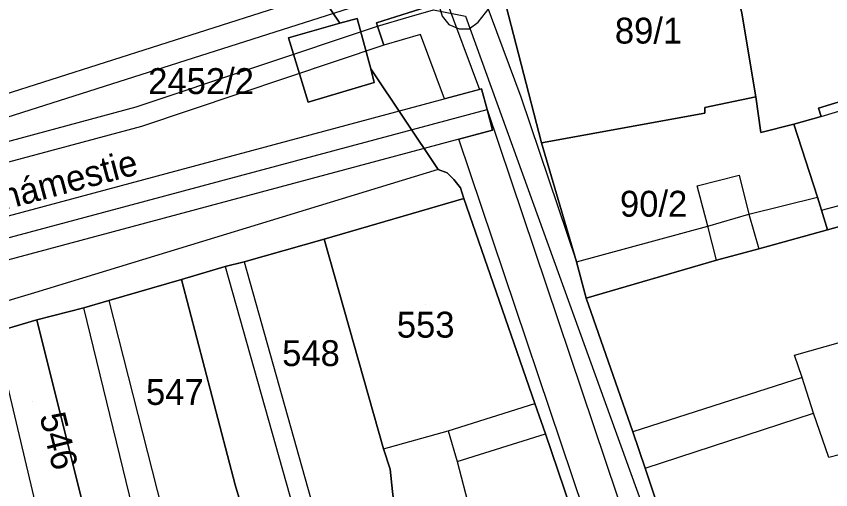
# Model space of a CAD drawing. Extents: x -263423 to -261326, y -1240067 to -1237864.
# Drawn here: x -262980.7 to -262917.7, y -1239574.4 to -1239537.8 of the extents above; entities that cross this region are included whole.
import ezdxf

# ---------------------------------------------------------------- set-up
doc = ezdxf.new("R2010")
doc.units = 0
for name, color, linetype in [('body_kn', 7, 'Continuous'), ('kladpar_druhypozemkov', 7, 'Continuous'), ('kladpar_hranice', 7, 'Continuous'), ('kladpar_parcelnecisla', 7, 'Continuous'), ('kladpar_plochy', 7, 'Continuous'), ('kladpar_sipky', 7, 'Continuous'), ('popisy', 7, 'Continuous'), ('tarchy_linie', 7, 'Continuous'), ('zappar_hrandruhpozemk', 7, 'Continuous')]:
    doc.layers.add(name, color=color, linetype=linetype)

msp = doc.modelspace()

# ---------------------------------------------------------------- linework, layer by layer
at = {"layer": 'body_kn'}
for p, q in [((-262954.35, -1239537.98), (-262954.35, -1239537.98)), ((-262950.32, -1239537.86), (-262950.32, -1239537.86)), ((-262955.69, -1239538.35), (-262955.69, -1239538.35)), ((-262955.69, -1239538.35), (-262955.69, -1239538.35)), ((-262952.85, -1239538.33), (-262952.85, -1239538.33)), ((-262952.77, -1239538.58), (-262952.77, -1239538.58)), ((-262952.77, -1239538.58), (-262952.77, -1239538.58)), ((-262947.27, -1239538.46), (-262947.27, -1239538.46)), ((-262946.45, -1239538.78), (-262946.45, -1239538.78)), ((-262946.45, -1239538.78), (-262946.45, -1239538.78)), ((-262945.68, -1239538.79), (-262945.68, -1239538.79)), ((-262944.98, -1239538.28), (-262944.98, -1239538.28)), ((-262949.46, -1239539.22), (-262949.46, -1239539.22)), ((-262959.65, -1239539.48), (-262959.65, -1239539.48)), ((-262952.28, -1239540.05), (-262952.28, -1239540.05)), ((-262953.28, -1239541.87), (-262953.28, -1239541.87)), ((-262953.03, -1239542.95), (-262953.03, -1239542.95)), ((-262944.88, -1239543.48), (-262944.88, -1239543.48)), ((-262944.73, -1239543.44), (-262944.73, -1239543.44)), ((-262958.13, -1239544.45), (-262958.13, -1239544.45)), ((-262947.59, -1239544.21), (-262947.59, -1239544.21)), ((-262941.68, -1239544.05), (-262941.68, -1239544.05)), ((-262923.51, -1239544.06), (-262923.51, -1239544.06)), ((-262923.51, -1239544.06), (-262923.51, -1239544.06)), ((-262971.43, -1239544.83), (-262971.43, -1239544.83)), ((-262944.3, -1239545.03), (-262944.3, -1239545.03)), ((-262944.3, -1239545.03), (-262944.3, -1239545.03)), ((-262927.47, -1239544.87), (-262927.47, -1239544.87)), ((-262918.67, -1239544.92), (-262918.67, -1239544.92)), ((-262927.47, -1239545.32), (-262927.47, -1239545.32)), ((-262918.48, -1239545.56), (-262918.48, -1239545.56)), ((-262918.48, -1239545.56), (-262918.48, -1239545.56)), ((-262971.03, -1239546.33), (-262971.03, -1239546.33)), ((-262920.57, -1239546.15), (-262920.57, -1239546.15)), ((-262943.87, -1239546.62), (-262943.87, -1239546.62)), ((-262923.14, -1239546.81), (-262923.14, -1239546.81)), ((-262946.48, -1239547.32), (-262946.48, -1239547.32)), ((-262940.1, -1239547.61), (-262940.1, -1239547.61)), ((-262940.1, -1239547.61), (-262940.1, -1239547.61)), ((-262948.08, -1239549.67), (-262948.08, -1239549.67)), ((-262948.08, -1239549.67), (-262948.08, -1239549.67)), ((-262947.38, -1239549.93), (-262947.38, -1239549.93)), ((-262924.81, -1239550.11), (-262924.81, -1239550.11)), ((-262946.87, -1239550.44), (-262946.87, -1239550.44)), ((-262946.36, -1239551.08), (-262946.36, -1239551.08)), ((-262928.06, -1239550.92), (-262928.06, -1239550.92)), ((-262946.11, -1239551.91), (-262946.11, -1239551.91)), ((-262946.11, -1239551.91), (-262946.11, -1239551.91)), ((-262918.76, -1239551.8), (-262918.76, -1239551.8)), ((-262924.05, -1239553.11), (-262924.05, -1239553.11)), ((-262918.44, -1239552.82), (-262918.44, -1239552.82)), ((-262918.44, -1239552.82), (-262918.44, -1239552.82)), ((-262927.24, -1239554.05), (-262927.24, -1239554.05)), ((-262917.99, -1239554.32), (-262917.99, -1239554.32)), ((-262917.99, -1239554.32), (-262917.99, -1239554.32)), ((-262956.89, -1239555.04), (-262956.89, -1239555.04)), ((-262923.3, -1239555.79), (-262923.3, -1239555.79)), ((-262963.09, -1239556.79), (-262963.09, -1239556.79)), ((-262963.09, -1239556.79), (-262963.09, -1239556.79)), ((-262937.39, -1239556.8), (-262937.39, -1239556.8)), ((-262937.39, -1239556.8), (-262937.39, -1239556.8)), ((-262926.55, -1239556.66), (-262926.55, -1239556.66)), ((-262926.55, -1239556.66), (-262926.55, -1239556.66)), ((-262964.55, -1239557.16), (-262964.55, -1239557.16)), ((-262964.55, -1239557.16), (-262964.55, -1239557.16)), ((-262967.94, -1239558.17), (-262967.94, -1239558.17)), ((-262967.94, -1239558.17), (-262967.94, -1239558.17)), ((-262979.29, -1239559.19), (-262979.29, -1239559.19)), ((-262973.55, -1239559.79), (-262973.55, -1239559.79)), ((-262973.55, -1239559.79), (-262973.55, -1239559.79)), ((-262936.63, -1239559.6), (-262936.63, -1239559.6)), ((-262975.47, -1239560.36), (-262975.47, -1239560.36)), ((-262979.11, -1239561.29), (-262979.11, -1239561.29)), ((-262920.52, -1239564.02), (-262920.52, -1239564.02)), ((-262920.52, -1239564.02), (-262920.52, -1239564.02)), ((-262919.95, -1239565.74), (-262919.95, -1239565.74)), ((-262919.95, -1239565.74), (-262919.95, -1239565.74)), ((-262940.62, -1239567.74), (-262940.62, -1239567.74)), ((-262919.07, -1239568.49), (-262919.07, -1239568.49)), ((-262947.32, -1239569.87), (-262947.32, -1239569.87)), ((-262939.79, -1239570.1), (-262939.79, -1239570.1)), ((-262933.04, -1239569.94), (-262933.04, -1239569.94)), ((-262952.3, -1239571.25), (-262952.3, -1239571.25)), ((-262952.3, -1239571.25), (-262952.3, -1239571.25)), ((-262917.87, -1239571.93), (-262917.87, -1239571.93)), ((-262946.62, -1239572.23), (-262946.62, -1239572.23)), ((-262932.09, -1239572.75), (-262932.09, -1239572.75)), ((-262932.09, -1239572.75), (-262932.09, -1239572.75)), ((-262951.79, -1239572.84), (-262951.79, -1239572.84)), ((-262963.78, -1239574.05), (-262963.78, -1239574.05))]:
    msp.add_line(p, q, dxfattribs=at)
at = {"layer": 'kladpar_druhypozemkov'}
for p, q in [((-262955.77, -1239541.66), (-262955.77, -1239541.66)), ((-262931.45, -1239551.21), (-262931.45, -1239551.21)), ((-262949.06, -1239560.12), (-262949.06, -1239560.12)), ((-262958.07, -1239562.56), (-262958.07, -1239562.56)), ((-262968.77, -1239565.66), (-262968.77, -1239565.66)), ((-262979.47, -1239567.56), (-262979.47, -1239567.56))]:
    msp.add_line(p, q, dxfattribs=at)
at = {"layer": 'kladpar_hranice'}
for points in [[(-262935.95, -1239581.4), (-262939.79, -1239570.1), (-262940.62, -1239567.74), (-262946.11, -1239551.91), (-262946.36, -1239551.08), (-262946.87, -1239550.44), (-262947.38, -1239549.93), (-262948.08, -1239549.67), (-262953.28, -1239541.87), (-262954.35, -1239537.98), (-262955.69, -1239538.35), (-262964.64, -1239525.12), (-262966.02, -1239520.78), (-262966.85, -1239521.03), (-262967.56, -1239521.21), (-262969.22, -1239521.78), (-262984.05, -1239464.66)], [(-262965.51, -1239465.42), (-262962.58, -1239476.73), (-262961.82, -1239479.55), (-262957.93, -1239492.91), (-262955.74, -1239500.08), (-262954.99, -1239502.36), (-262952.85, -1239509), (-262951.27, -1239514.04), (-262950.07, -1239517.61), (-262948.43, -1239523.23), (-262945.27, -1239531.91), (-262943.25, -1239535.42), (-262940.1, -1239547.61), (-262937.39, -1239556.8), (-262936.63, -1239559.6), (-262933.04, -1239569.94), (-262932.09, -1239572.75), (-262928.43, -1239583.67)], [(-262964.64, -1239525.12), (-262955.69, -1239538.35), (-262959.65, -1239539.48), (-262958.13, -1239544.45), (-262953.03, -1239542.95), (-262953.28, -1239541.87), (-262948.08, -1239549.67), (-262947.38, -1239549.93), (-262946.87, -1239550.44), (-262946.36, -1239551.08), (-262946.11, -1239551.91), (-262956.89, -1239555.04), (-262963.09, -1239556.79), (-262964.55, -1239557.16), (-262967.94, -1239558.17), (-262973.55, -1239559.79), (-262975.47, -1239560.36), (-262979.11, -1239561.29), (-262982.36, -1239562.23)], [(-262923.51, -1239544.06), (-262927.47, -1239544.87), (-262927.47, -1239545.32), (-262940.1, -1239547.61), (-262943.25, -1239535.42), (-262926.24, -1239530.63)], [(-262926.24, -1239530.63), (-262924.6, -1239537.58), (-262923.51, -1239544.06)], [(-262923.51, -1239544.06), (-262924.6, -1239537.58), (-262926.24, -1239530.63)], [(-262869.06, -1239540.52), (-262844.5, -1239533.52), (-262841.03, -1239544.11), (-262840.53, -1239545.7), (-262836.49, -1239558.34), (-262849.7, -1239561.9), (-262861.12, -1239565.66), (-262879.23, -1239570.41), (-262884.4, -1239571.98), (-262891.48, -1239573.92), (-262893.14, -1239574.42), (-262895.06, -1239574.86), (-262928.43, -1239583.67), (-262932.09, -1239572.75), (-262933.04, -1239569.94), (-262936.63, -1239559.6), (-262926.55, -1239556.66), (-262923.3, -1239555.79), (-262917.99, -1239554.32), (-262895.92, -1239548.22), (-262869.06, -1239540.52)], [(-262955.69, -1239538.35), (-262954.35, -1239537.98), (-262953.28, -1239541.87), (-262953.03, -1239542.95), (-262958.13, -1239544.45), (-262959.65, -1239539.48), (-262955.69, -1239538.35)], [(-262913.95, -1239543.48), (-262918.67, -1239544.92), (-262918.48, -1239545.56), (-262920.57, -1239546.15), (-262923.14, -1239546.81), (-262923.51, -1239544.06)], [(-262917.99, -1239554.32), (-262918.44, -1239552.82), (-262918.76, -1239551.8), (-262920.57, -1239546.15), (-262918.48, -1239545.56), (-262918.67, -1239544.92), (-262913.95, -1239543.48)], [(-262940.1, -1239547.61), (-262927.47, -1239545.32), (-262927.47, -1239544.87), (-262923.51, -1239544.06), (-262923.14, -1239546.81), (-262920.57, -1239546.15), (-262918.76, -1239551.8), (-262918.44, -1239552.82), (-262917.99, -1239554.32), (-262923.3, -1239555.79), (-262926.55, -1239556.66), (-262936.63, -1239559.6), (-262937.39, -1239556.8), (-262940.1, -1239547.61)], [(-262895.92, -1239548.22), (-262917.99, -1239554.32)], [(-262946.11, -1239551.91), (-262940.62, -1239567.74), (-262939.79, -1239570.1), (-262935.95, -1239581.4), (-262945.07, -1239583.13), (-262944.44, -1239584.67), (-262949.54, -1239585.6), (-262950.55, -1239581.32), (-262951.11, -1239578.71), (-262951.61, -1239574.56), (-262951.79, -1239572.84), (-262952.3, -1239571.25), (-262956.89, -1239555.04), (-262946.11, -1239551.91)], [(-262952.3, -1239571.25), (-262951.79, -1239572.84), (-262951.61, -1239574.56), (-262951.11, -1239578.71), (-262950.55, -1239581.32), (-262949.54, -1239585.6), (-262954.9, -1239586.97), (-262959.31, -1239588.09), (-262960.31, -1239584.2), (-262960.63, -1239583.05), (-262961.07, -1239583.05), (-262963.03, -1239576.54), (-262963.78, -1239574.05), (-262967.94, -1239558.17), (-262964.55, -1239557.16), (-262963.09, -1239556.79), (-262956.89, -1239555.04), (-262952.3, -1239571.25)], [(-262967.94, -1239558.17), (-262963.78, -1239574.05), (-262963.03, -1239576.54), (-262961.07, -1239583.05), (-262960.63, -1239583.05), (-262960.31, -1239584.2), (-262959.31, -1239588.09), (-262971.11, -1239591.16), (-262972.25, -1239587.01), (-262974.89, -1239578.2), (-262979.11, -1239561.29), (-262975.47, -1239560.36), (-262973.55, -1239559.79), (-262967.94, -1239558.17)], [(-262974.89, -1239578.2), (-262972.25, -1239587.01), (-262971.11, -1239591.16), (-262976.09, -1239593.1), (-262977.35, -1239588.89), (-262980.13, -1239579.7), (-262985.3, -1239563.04), (-262982.36, -1239562.23), (-262979.11, -1239561.29), (-262974.89, -1239578.2)]]:
    msp.add_lwpolyline(points, dxfattribs=at)
at = {"layer": 'kladpar_plochy'}
for points in [[(-262935.95, -1239581.4), (-262939.79, -1239570.1), (-262940.62, -1239567.74), (-262946.11, -1239551.91), (-262946.36, -1239551.08), (-262946.87, -1239550.44), (-262947.38, -1239549.93), (-262948.08, -1239549.67), (-262953.28, -1239541.87), (-262954.35, -1239537.98), (-262955.69, -1239538.35), (-262964.64, -1239525.12), (-262966.02, -1239520.78), (-262966.85, -1239521.03), (-262967.56, -1239521.21), (-262969.22, -1239521.78), (-262984.05, -1239464.66)], [(-262965.51, -1239465.42), (-262962.58, -1239476.73), (-262961.82, -1239479.55), (-262957.93, -1239492.91), (-262955.74, -1239500.08), (-262954.99, -1239502.36), (-262952.85, -1239509), (-262951.27, -1239514.04), (-262950.07, -1239517.61), (-262948.43, -1239523.23), (-262945.27, -1239531.91), (-262943.25, -1239535.42), (-262940.1, -1239547.61), (-262937.39, -1239556.8), (-262936.63, -1239559.6), (-262933.04, -1239569.94), (-262932.09, -1239572.75), (-262928.43, -1239583.67)], [(-262964.64, -1239525.12), (-262955.69, -1239538.35), (-262959.65, -1239539.48), (-262958.13, -1239544.45), (-262953.03, -1239542.95), (-262953.28, -1239541.87), (-262948.08, -1239549.67), (-262947.38, -1239549.93), (-262946.87, -1239550.44), (-262946.36, -1239551.08), (-262946.11, -1239551.91), (-262956.89, -1239555.04), (-262963.09, -1239556.79), (-262964.55, -1239557.16), (-262967.94, -1239558.17), (-262973.55, -1239559.79), (-262975.47, -1239560.36), (-262979.11, -1239561.29), (-262982.36, -1239562.23)], [(-262895.92, -1239548.22), (-262917.99, -1239554.32), (-262918.44, -1239552.82), (-262918.76, -1239551.8), (-262920.57, -1239546.15), (-262918.48, -1239545.56), (-262918.67, -1239544.92), (-262913.95, -1239543.48)]]:
    msp.add_lwpolyline(points, dxfattribs=at)
for points in [[(-262917.14, -1239528.13), (-262916.09, -1239533.53), (-262916.62, -1239533.75), (-262914.63, -1239540.59), (-262913.95, -1239543.48), (-262918.67, -1239544.92), (-262918.48, -1239545.56), (-262920.57, -1239546.15), (-262923.14, -1239546.81), (-262923.51, -1239544.06), (-262924.6, -1239537.58), (-262926.24, -1239530.63)], [(-262926.24, -1239530.63), (-262924.6, -1239537.58), (-262923.51, -1239544.06), (-262927.47, -1239544.87), (-262927.47, -1239545.32), (-262940.1, -1239547.61), (-262943.25, -1239535.42)], [(-262869.06, -1239540.52), (-262844.5, -1239533.52), (-262841.03, -1239544.11), (-262840.53, -1239545.7), (-262836.49, -1239558.34), (-262849.7, -1239561.9), (-262861.12, -1239565.66), (-262879.23, -1239570.41), (-262884.4, -1239571.98), (-262891.48, -1239573.92), (-262893.14, -1239574.42), (-262895.06, -1239574.86), (-262928.43, -1239583.67), (-262932.09, -1239572.75), (-262933.04, -1239569.94), (-262936.63, -1239559.6), (-262926.55, -1239556.66), (-262923.3, -1239555.79), (-262917.99, -1239554.32), (-262895.92, -1239548.22)], [(-262955.69, -1239538.35), (-262954.35, -1239537.98), (-262953.28, -1239541.87), (-262953.03, -1239542.95), (-262958.13, -1239544.45), (-262959.65, -1239539.48)], [(-262940.1, -1239547.61), (-262927.47, -1239545.32), (-262927.47, -1239544.87), (-262923.51, -1239544.06), (-262923.14, -1239546.81), (-262920.57, -1239546.15), (-262918.76, -1239551.8), (-262918.44, -1239552.82), (-262917.99, -1239554.32), (-262923.3, -1239555.79), (-262926.55, -1239556.66), (-262936.63, -1239559.6), (-262937.39, -1239556.8)], [(-262946.11, -1239551.91), (-262940.62, -1239567.74), (-262939.79, -1239570.1), (-262935.95, -1239581.4), (-262945.07, -1239583.13), (-262944.44, -1239584.67), (-262949.54, -1239585.6), (-262950.55, -1239581.32), (-262951.11, -1239578.71), (-262951.61, -1239574.56), (-262951.79, -1239572.84), (-262952.3, -1239571.25), (-262956.89, -1239555.04)], [(-262952.3, -1239571.25), (-262951.79, -1239572.84), (-262951.61, -1239574.56), (-262951.11, -1239578.71), (-262950.55, -1239581.32), (-262949.54, -1239585.6), (-262954.9, -1239586.97), (-262959.31, -1239588.09), (-262960.31, -1239584.2), (-262960.63, -1239583.05), (-262961.07, -1239583.05), (-262963.03, -1239576.54), (-262963.78, -1239574.05), (-262967.94, -1239558.17), (-262964.55, -1239557.16), (-262963.09, -1239556.79), (-262956.89, -1239555.04)], [(-262967.94, -1239558.17), (-262963.78, -1239574.05), (-262963.03, -1239576.54), (-262961.07, -1239583.05), (-262960.63, -1239583.05), (-262960.31, -1239584.2), (-262959.31, -1239588.09), (-262971.11, -1239591.16), (-262972.25, -1239587.01), (-262974.89, -1239578.2), (-262979.11, -1239561.29), (-262975.47, -1239560.36), (-262973.55, -1239559.79)], [(-262974.89, -1239578.2), (-262972.25, -1239587.01), (-262971.11, -1239591.16), (-262976.09, -1239593.1), (-262977.35, -1239588.89), (-262980.13, -1239579.7), (-262985.3, -1239563.04), (-262982.36, -1239562.23), (-262979.11, -1239561.29)]]:
    msp.add_lwpolyline(points, close=True, dxfattribs=at)
at = {"layer": 'kladpar_sipky'}
msp.add_line((-262957.62, -1239541.79), (-262957.62, -1239541.79), dxfattribs=at)
at = {"layer": 'tarchy_linie'}
msp.add_line((-262948.06, -1239534.97), (-262944.88, -1239543.48), dxfattribs=at)
for points in [[(-262996.25, -1239368.2), (-262982.01, -1239418.22), (-262971.42, -1239457.36), (-262966.51, -1239473.04), (-262962.2, -1239489.84), (-262952.7, -1239523.45), (-262946.54, -1239534.09), (-262945.44, -1239533.99), (-262944.48, -1239536.54), (-262941.68, -1239544.05), (-262937.39, -1239556.8), (-262936.63, -1239559.6), (-262933.04, -1239569.94), (-262932.09, -1239572.75), (-262928.43, -1239583.67)], [(-262935.07, -1239581.22), (-262946.48, -1239547.32), (-262943.87, -1239546.62), (-262944.3, -1239545.03), (-262944.73, -1239543.44), (-262944.88, -1239543.48), (-262947.59, -1239544.21), (-262949.46, -1239539.22), (-262952.28, -1239540.05), (-262952.77, -1239538.58), (-262952.85, -1239538.33), (-262950.4, -1239537.55), (-262947.53, -1239536.64), (-262948.06, -1239534.97), (-262948.59, -1239533.3), (-262948.96, -1239533.42), (-262951.28, -1239534.16), (-262952.76, -1239534.63), (-262955.13, -1239526.23), (-262957.62, -1239521.94), (-262971.98, -1239470.84), (-262974.3, -1239461.67), (-263002.42, -1239467.19)], [(-262994.84, -1239548.07), (-262948.59, -1239533.3), (-262948.06, -1239534.97), (-262947.53, -1239536.64), (-262952.85, -1239538.33), (-262952.77, -1239538.58), (-262952.28, -1239540.05), (-262971.03, -1239546.33), (-262997.67, -1239553.47)], [(-263185.95, -1239572.52), (-263145.78, -1239566.85), (-263093.03, -1239558.66), (-263044.58, -1239553.16), (-263018.82, -1239552.67), (-262994.63, -1239549.81), (-262948.06, -1239534.97)], [(-262952.77, -1239538.58), (-262950.32, -1239537.86), (-262948.45, -1239537.31), (-262945.97, -1239537.82), (-262929.56, -1239583.21), (-262926.69, -1239589.69), (-262925.17, -1239595.04), (-262922.55, -1239607.14), (-262922.37, -1239609.59), (-262916.97, -1239626.37)], [(-263192.88, -1239575.95), (-263179.14, -1239573.04), (-263157.82, -1239569.8), (-263134.74, -1239566.33), (-263114.94, -1239563.73), (-263090.46, -1239559.7), (-263054.88, -1239555.38), (-263040.51, -1239554.18), (-263032.13, -1239554.16), (-263020, -1239554.28), (-263009.64, -1239553), (-262997.81, -1239551.93), (-262971.43, -1239544.83), (-262952.77, -1239538.58)], [(-263011.76, -1239565.02), (-263012.2, -1239563.43), (-263012.64, -1239561.84), (-262983.07, -1239553.7), (-262944.73, -1239543.44), (-262944.3, -1239545.03), (-262943.87, -1239546.62), (-262982.19, -1239556.88), (-263011.76, -1239565.02)], [(-263012.2, -1239563.43), (-262982.63, -1239555.29), (-262944.3, -1239545.03)], [(-262944.3, -1239545.03), (-262932.42, -1239580.33), (-262923.42, -1239609.49), (-262918.19, -1239626.73)]]:
    msp.add_lwpolyline(points, dxfattribs=at)
at = {"layer": 'zappar_hrandruhpozemk'}
for p, q in [((-262918.48, -1239545.56), (-262905.4, -1239541.67)), ((-262948.08, -1239549.67), (-262979.29, -1239559.19)), ((-262928.06, -1239550.92), (-262924.81, -1239550.11)), ((-262963.09, -1239556.79), (-262957.73, -1239575.87)), ((-262964.55, -1239557.16), (-262959.26, -1239575.92)), ((-262973.55, -1239559.79), (-262968.9, -1239578.1)), ((-262971.01, -1239578.67), (-262975.47, -1239560.36)), ((-262978.34, -1239579.2), (-262982.36, -1239562.23)), ((-262919.95, -1239565.74), (-262933.04, -1239569.94)), ((-262947.32, -1239569.87), (-262940.62, -1239567.74)), ((-262932.09, -1239572.75), (-262919.07, -1239568.49)), ((-262952.3, -1239571.25), (-262947.32, -1239569.87)), ((-262947.32, -1239569.87), (-262946.62, -1239572.23)), ((-262946.62, -1239572.23), (-262939.79, -1239570.1)), ((-262946.62, -1239572.23), (-262945.3, -1239577.21))]:
    msp.add_line(p, q, dxfattribs=at)
for points in [[(-262952, -1239522.19), (-262948.91, -1239532.91), (-262948.27, -1239532.78), (-262947.14, -1239536.29), (-262947.71, -1239536.67), (-262947.97, -1239537.12), (-262947.78, -1239537.82), (-262947.27, -1239538.46), (-262946.45, -1239538.78)], [(-262946.45, -1239538.78), (-262945.68, -1239538.79), (-262944.98, -1239538.28), (-262944.14, -1239537.2), (-262943.5, -1239536.12), (-262943.25, -1239535.42)], [(-262865.19, -1239546.34), (-262863.68, -1239551), (-262862.92, -1239553.68), (-262861.41, -1239558.78), (-262905.75, -1239570.66), (-262906.26, -1239568.94), (-262917.87, -1239571.93), (-262919.07, -1239568.49), (-262919.95, -1239565.74), (-262920.52, -1239564.02)], [(-262918.44, -1239552.82), (-262903.45, -1239548.82), (-262904.14, -1239546.46)], [(-262924.81, -1239550.11), (-262924.05, -1239553.11), (-262923.3, -1239555.79)], [(-262926.55, -1239556.66), (-262927.24, -1239554.05), (-262928.06, -1239550.92)], [(-262937.39, -1239556.8), (-262927.24, -1239554.05), (-262924.05, -1239553.11), (-262918.76, -1239551.8)], [(-262979.29, -1239559.19), (-263001.7, -1239565.89), (-263015.63, -1239569.93), (-263018.96, -1239558.4), (-263020.56, -1239559.73)], [(-262920.52, -1239564.02), (-262909.03, -1239560.77), (-262909.47, -1239559.11)]]:
    msp.add_lwpolyline(points, dxfattribs=at)

# ---------------------------------------------------------------- texts
at = {"layer": 'kladpar_parcelnecisla'}
for s, p in [('89/1', (-262934.42, -1239539.93)), ('2452/2', (-262970.505, -1239543.83)), ('90/2', (-262934.026, -1239553.31)), ('553', (-262951.282, -1239562.66)), ('548', (-262960.148, -1239564.86)), ('547', (-262970.677, -1239567.86))]:
    msp.add_text(s, height=2, dxfattribs=at).set_placement(p)
msp.add_text('546', height=2, rotation=284, dxfattribs=at).set_placement((-262978.92, -1239568.708))
at = {"layer": 'popisy'}
msp.add_text('Dominikánske námestie', height=2, rotation=15, dxfattribs=at).set_placement((-262998.57, -1239557.348))

doc.saveas('drawing.dxf')
